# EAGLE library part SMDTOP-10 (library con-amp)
AMP connector
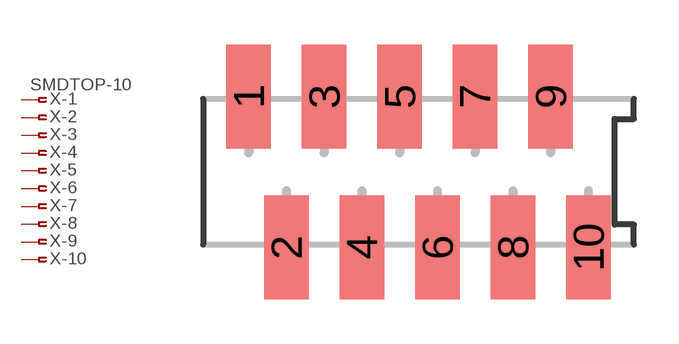
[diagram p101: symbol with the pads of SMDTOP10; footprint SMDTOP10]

Designator prefix X; gates -1=PIN-FV -2=PIN-F -3=PIN-F -4=PIN-F -5=PIN-F -6=PIN-F -7=PIN-F -8=PIN-F -9=PIN-F -10=PIN-F

## SMDTOP-10 (OC_FARNELL: unknown; OC_NEWARK: unknown)  [SMDTOP10]
1  -1:1  pas
2  -2:1  pas
3  -3:1  pas
4  -4:1  pas
5  -5:1  pas
6  -6:1  pas
7  -7:1  pas
8  -8:1  pas
9  -9:1  pas
10  -10:1  pas

## Footprint SMDTOP10 (pad centres in mm)
AMP connector
smd 1.5 x 3.5: 1 -5.715,2.54; 2 -4.445,-2.54; 3 -3.175,2.54; 4 -1.905,-2.54; 5 -0.635,2.54; 6 0.635,-2.54; 7 1.905,2.54; 8 3.175,-2.54; 9 4.445,2.54; 10 5.715,-2.54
